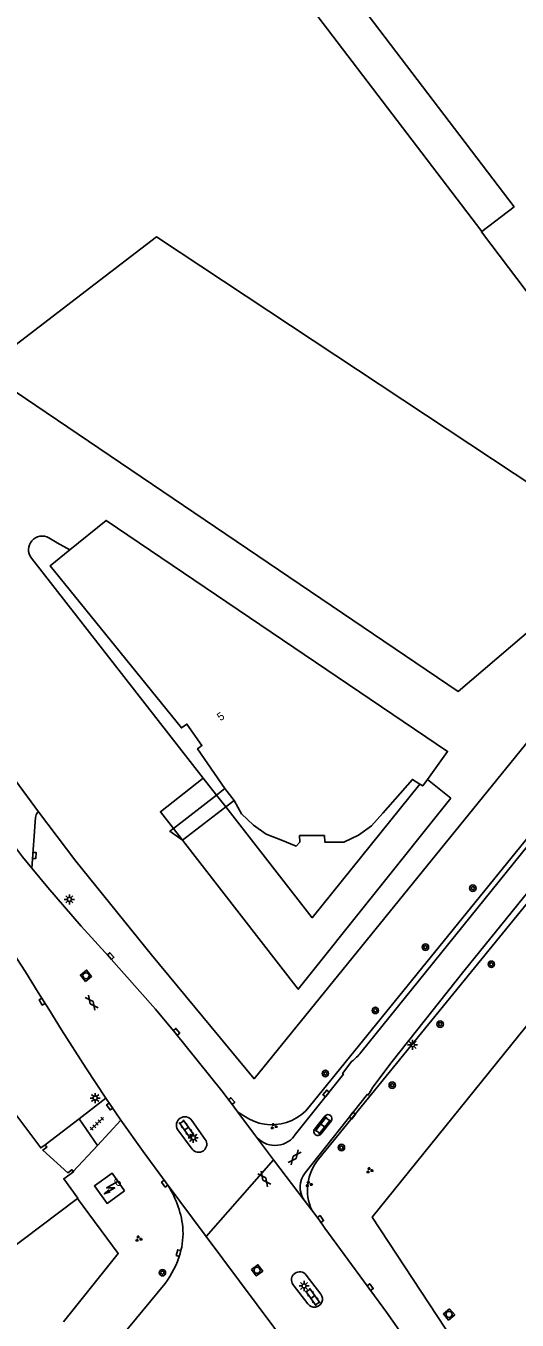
# Model space of a CAD drawing. Extents: x 126000 to 131009, y 393000 to 395500.
# Drawn here: x 130767.6 to 130828.7, y 394018 to 394178.9 of the extents above; entities that cross this region are included whole.
import ezdxf

# ---------------------------------------------------------------- set-up
doc = ezdxf.new("R2010")
doc.units = 0
for name, color, linetype in [('gg-afsc-hekwerk', 7, 'Continuous'), ('gg-afsc-muur', 7, 'Continuous'), ('gg-anno-huisnummerreeks BGT', 7, 'Continuous'), ('gg-bbg-bijgebouw', 7, 'Continuous'), ('gg-bbg-hoofdgebouw', 7, 'Continuous'), ('gg-bbg-onder overbouw', 7, 'Continuous'), ('gg-bbg-pand overbouw', 7, 'Continuous'), ('gg-knt-verharding', 7, 'Continuous'), ('gg-knt-verharding nz', 7, 'Continuous'), ('gg-kntw-bovenkant insteek waterloop', 7, 'Continuous'), ('gg-kntw-kademuur', 7, 'Continuous'), ('gt-grn-groengrens', 7, 'Continuous'), ('gt-grn-weggrens', 7, 'Continuous'), ('gt-symb-boom', 7, 'Continuous'), ('gt-symb-gesloten verharding', 7, 'Continuous'), ('gt-symb-groenvak', 7, 'Continuous'), ('gt-symb-klinker verharding', 7, 'Continuous'), ('gt-symb-kolk', 7, 'Continuous'), ('gt-symb-lichtmast', 7, 'Continuous'), ('gt-symb-rioolschacht', 7, 'Continuous'), ('gt-symb-tegel verharding', 7, 'Continuous'), ('gt-symb-trafo symbool', 7, 'Continuous')]:
    doc.layers.add(name, color=color, linetype=linetype)

# ---------------------------------------------------------------- blocks, each defined once
blk = doc.blocks.new('gt0-KOLK')
at = {"layer": 'gt-symb-kolk'}
blk.add_lwpolyline([(0, 0), (0.38, 0), (0.38, 0.4), (-0.37, 0.4), (-0.37, 0), (0, 0)], dxfattribs=at)
blk = doc.blocks.new('gt0-KL1')
at = {"layer": 'gt-symb-klinker verharding'}
for p, q in [((-1.15, 0.3), (1.15, 0.3)), ((-1, -0.3), (-1, 0.3)), ((-0.5, 0.3), (-0.5, 0.45)), ((0, -0.3), (0, 0.3)), ((0.5, 0.3), (0.5, 0.45)), ((1, -0.3), (1, 0.3)), ((-1.15, -0.3), (1.15, -0.3)), ((-0.5, -0.45), (-0.5, -0.3)), ((0.5, -0.45), (0.5, -0.3))]:
    blk.add_line(p, q, dxfattribs=at)
blk = doc.blocks.new('gt0-BOOM')
at = {"layer": 'gt-symb-boom'}
for radius in [0.4, 0.2]:
    blk.add_circle((0, 0), radius, dxfattribs=at)
blk = doc.blocks.new('gt0-GRVAK')
at = {"layer": 'gt-symb-groenvak'}
for p, q in [((-0.11, 0.19), (-0.23, 0.24)), ((-0.18, 0.15), (0.09, 0.15)), ((-0.09, 0.21), (-0.16, 0.32)), ((-0.05, 0.21), (-0.05, 0.39)), ((0, 0.21), (0.06, 0.32)), ((0.01, 0.19), (0.13, 0.24)), ((0.26, -0.05), (0.2, 0.06)), ((0.3, -0.05), (0.3, 0.13)), ((0.35, -0.05), (0.41, 0.06)), ((-0.25, -0.23), (-0.36, -0.18)), ((-0.32, -0.26), (-0.05, -0.26)), ((-0.23, -0.21), (-0.29, -0.1)), ((-0.18, -0.2), (-0.18, -0.02)), ((-0.14, -0.21), (-0.07, -0.1)), ((-0.12, -0.23), (0, -0.18)), ((0.24, -0.07), (0.12, -0.02)), ((0.17, -0.11), (0.44, -0.11)), ((0.37, -0.07), (0.49, -0.02))]:
    blk.add_line(p, q, dxfattribs=at)
blk = doc.blocks.new('gt0-RS')
at = {"layer": 'gt-symb-rioolschacht'}
blk.add_lwpolyline([(-0.5, -0.5), (0.5, -0.5), (0.5, 0.5), (-0.5, 0.5)], close=True, dxfattribs=at)
blk.add_circle((0, 0), 0.375, dxfattribs=at)
blk = doc.blocks.new('gt0-GESVH1')
at = {"layer": 'gt-symb-gesloten verharding'}
for p, q in [((-0.99, -0.26), (0.01, 0.24)), ((0.01, -0.26), (-0.99, 0.24)), ((0.01, 0.24), (1.01, -0.26)), ((1.01, 0.24), (0.01, -0.26))]:
    blk.add_line(p, q, dxfattribs=at)
blk = doc.blocks.new('gt0-LMAST')
at = {"layer": 'gt-symb-lichtmast'}
for p, q in [((-0.18, 0.17), (-0.45, 0.44)), ((0, 0.25), (0, 0.62)), ((0.17, 0.17), (0.44, 0.44)), ((-0.25, 0), (-0.63, 0)), ((-0.18, -0.18), (-0.45, -0.45)), ((0, -0.25), (0, -0.63)), ((0.44, -0.45), (0.17, -0.18)), ((0.25, 0), (0.62, 0))]:
    blk.add_line(p, q, dxfattribs=at)
blk.add_circle((0, 0), 0.25, dxfattribs=at)
blk = doc.blocks.new('gt0-TEG1')
at = {"layer": 'gt-symb-tegel verharding'}
for p, q in [((-1.12, 0), (1.12, 0)), ((-0.9, -0.25), (-0.9, 0.25)), ((-0.45, -0.25), (-0.45, 0.25)), ((0, -0.25), (0, 0.25)), ((0.45, -0.25), (0.45, 0.25)), ((0.9, -0.25), (0.9, 0.25))]:
    blk.add_line(p, q, dxfattribs=at)
blk = doc.blocks.new('gt0-HSP')
at = {"layer": 'gt-symb-trafo symbool'}
for points in [[(0.77, 0.75), (-0.53, 0), (0.47, 0), (-0.83, -0.75)], [(-0.22, -0.24), (-0.83, -0.75), (-0.08, -0.48)]]:
    blk.add_lwpolyline(points, dxfattribs=at)

msp = doc.modelspace()

# ---------------------------------------------------------------- linework, layer by layer
at = {"layer": 'gg-afsc-hekwerk'}
for p, q in [((130782.38, 394208.28), (130824.29, 394153.36)), ((130769.13, 394081.19), (130766.27, 394085.09))]:
    msp.add_line(p, q, dxfattribs=at)
for points in [[(130847.03, 394110.9), (130795.94, 394047.99), (130783.2, 394063.41), (130773.77, 394075.06), (130769.13, 394081.19)], [(130857.9, 394089.3), (130810.65, 394030.76), (130830.86, 394000)], [(130773.98, 394033.09), (130779.05, 394026.25), (130772.23, 394017.75)]]:
    msp.add_lwpolyline(points, dxfattribs=at)
at = {"layer": 'gg-afsc-muur'}
for p, q in [((130770.42, 394115.26), (130771.45, 394114.66)), ((130771.45, 394114.66), (130773.02, 394113.77)), ((130789.63, 394085.36), (130768.25, 394112.75))]:
    msp.add_line(p, q, dxfattribs=at)
msp.add_arc((130769.58, 394113.79), 1.69, 60.2136, 217.9768, dxfattribs=at)
at = {"layer": 'gg-bbg-bijgebouw'}
msp.add_lwpolyline([(130776.19, 394146.86), (130783.82, 394152.69), (130842.25, 394114.02), (130821.34, 394096.16), (130762.19, 394136.16), (130776.19, 394146.86)], dxfattribs=at)
at = {"layer": 'gg-bbg-hoofdgebouw'}
msp.add_line((130828.31, 394156.42), (130824.29, 394153.36), dxfattribs=at)
for points in [[(130808.18, 394220.62), (130807.84, 394220.37), (130811.77, 394215.21), (130811.85, 394215.26), (130812.68, 394214.15), (130794.75, 394200.51), (130828.31, 394156.42)], [(130847.63, 394122.45), (130824.25, 394153.33), (130824.29, 394153.36)], [(130817.51, 394085.21), (130820.02, 394088.7), (130777.54, 394117.43), (130773.02, 394113.77)], [(130792.3, 394084.07), (130788.93, 394089.02), (130789.46, 394089.43), (130787.6, 394092.1), (130786.91, 394091.62), (130770.59, 394111.8), (130773.02, 394113.77)], [(130816.57, 394084.63), (130815.65, 394085.22), (130811.97, 394081), (130810.56, 394079.46), (130808.92, 394078.27), (130807.11, 394077.41), (130804.76, 394077.41), (130804.69, 394078.23), (130801.6, 394078.23), (130801.65, 394077.42), (130801.19, 394076.93), (130799.27, 394077.72), (130797.47, 394078.39), (130795.89, 394079.53), (130794.4, 394080.93), (130793.46, 394082.6)], [(130816.57, 394084.63), (130816.93, 394084.4), (130817.51, 394085.21)], [(130741.04, 394077.22), (130769.42, 394039.39), (130769.98, 394039.75)], [(130737.87, 394043.54), (130755.87, 394019.46), (130773.98, 394033.09)], [(130769.98, 394039.75), (130770.17, 394039.49), (130769.66, 394039.11), (130772.79, 394036.29), (130773.29, 394036.67), (130773.46, 394036.44)], [(130773.98, 394033.09), (130774.04, 394033.14), (130772.27, 394035.54), (130773.49, 394036.41), (130773.46, 394036.44)], [(130779.82, 394034.06), (130777.67, 394032.48), (130776.08, 394034.66), (130778.28, 394036.25), (130779.82, 394034.06)]]:
    msp.add_lwpolyline(points, dxfattribs=at)
at = {"layer": 'gg-bbg-onder overbouw'}
msp.add_line((130792.3, 394084.07), (130793.46, 394082.6), dxfattribs=at)
at = {"layer": 'gg-bbg-pand overbouw'}
for p, q in [((130791.27, 394083.27), (130792.3, 394084.07)), ((130791.27, 394083.27), (130785.93, 394079.11)), ((130793.46, 394082.6), (130792.42, 394081.8)), ((130787.05, 394077.68), (130792.42, 394081.8))]:
    msp.add_line(p, q, dxfattribs=at)
msp.add_lwpolyline([(130787.05, 394077.68), (130785.47, 394078.76), (130785.93, 394079.11)], dxfattribs=at)
at = {"layer": 'gg-knt-verharding'}
for p, q in [((130769.01, 394081.1), (130769.13, 394081.19)), ((130768.75, 394080.49), (130768.3, 394074.19)), ((130777.52, 394045.56), (130774.18, 394042.99)), ((130779.38, 394042.84), (130777.52, 394045.56)), ((130793.94, 394043.82), (130796.13, 394040.87)), ((130774.18, 394042.99), (130769.98, 394039.75)), ((130776.48, 394039.7), (130779.38, 394042.84)), ((130788.2, 394042.78), (130789.88, 394040.44)), ((130804.75, 394043.35), (130803.51, 394041.77)), ((130804.27, 394041.11), (130805.52, 394042.72)), ((130788.25, 394039.24), (130786.46, 394041.65)), ((130773.46, 394036.44), (130776.48, 394039.7)), ((130790, 394028.37), (130785, 394035.05)), ((130803.14, 394031.62), (130802.17, 394032.89)), ((130800.57, 394014.22), (130790, 394028.37)), ((130802.42, 394023.55), (130804.25, 394021.19)), ((130778.55, 394014.83), (130784.87, 394022.52)), ((130802.64, 394019.99), (130800.79, 394022.37))]:
    msp.add_line(p, q, dxfattribs=at)
for points in [[(130868.2, 394118.01), (130856.33, 394103.62), (130847.32, 394092.59), (130822.05, 394061.38), (130813.14, 394050.14), (130810.73, 394046.93), (130810.15, 394045.96), (130810.04, 394046.05), (130802.3, 394036.29)], [(130809.22, 394051.26), (130830.96, 394078.16), (130853.82, 394106.34), (130853.94, 394106.64), (130853.99, 394106.95)], [(130768.3, 394074.19), (130767.15, 394075.58), (130764, 394079.72), (130759.54, 394085.8)], [(130791.92, 394046.49), (130786.15, 394053.7), (130783.68, 394056.62), (130777.82, 394063.25), (130774.44, 394066.98), (130770.3, 394071.77), (130768.3, 394074.19)], [(130764.2, 394066.33), (130765.89, 394063.79), (130767.53, 394061.27), (130769.11, 394058.73), (130769.75, 394057.68), (130770.42, 394056.64), (130772.01, 394054.08)], [(130777.52, 394045.56), (130775.02, 394049.34), (130772.01, 394054.08)], [(130800.95, 394040.87), (130807.06, 394048.55), (130806.96, 394048.63), (130808.1, 394050.16)], [(130791.92, 394046.49), (130792.84, 394045.27), (130793, 394045.09), (130793.94, 394043.82)], [(130785, 394035.05), (130782.16, 394038.92), (130779.38, 394042.84)], [(130804.76, 394029.42), (130804.04, 394030.43), (130803.14, 394031.62)], [(130804.76, 394029.42), (130812.41, 394018.97), (130813.99, 394016.7), (130815.89, 394013.76), (130819.98, 394007.25)]]:
    msp.add_lwpolyline(points, dxfattribs=at)
for centre, radius, start, end in [((130769.82, 394080.39), 1.07, 138.6022, 174.683), ((130805.43, 394054.02), 4.69, 304.614, 323.8334), ((130787.33, 394042.21), 1.04, 33.3243, 212.6033), ((130805.13, 394043.03), 0.501, 321.7935, 140.2076), ((130798.54, 394042.76), 3.07, 218.1447, 321.7839), ((130803.88, 394041.43), 0.504, 137.9362, 320.1949), ((130789.05, 394039.86), 1.02, 217.2913, 35.1739), ((130804.57, 394034.5), 2.89, 141.8352, 213.849), ((130775.27, 394028.24), 11.88, 6.2599, 34.9456), ((130778.13, 394028.78), 8.98, 343.5907, 4.8262), ((130775.7, 394029.45), 11.5, 322.9308, 343.8039), ((130801.61, 394022.96), 1.01, 36.1409, 215.7295), ((130803.46, 394020.57), 1, 215.2896, 38.1078)]:
    msp.add_arc(centre, radius, start, end, dxfattribs=at)
at = {"layer": 'gg-knt-verharding nz'}
for p, q in [((130798.37, 394037.92), (130796.13, 394040.87)), ((130802.17, 394032.89), (130798.37, 394037.92))]:
    msp.add_line(p, q, dxfattribs=at)
at = {"layer": 'gg-kntw-bovenkant insteek waterloop'}
for p, q in [((130820.43, 394082.87), (130817.51, 394085.21)), ((130787.05, 394077.68), (130785.93, 394079.11))]:
    msp.add_line(p, q, dxfattribs=at)
for points in [[(130789.63, 394085.36), (130784.3, 394081.2), (130785.93, 394079.11)], [(130820.43, 394082.87), (130801.45, 394059.11), (130787.05, 394077.68)]]:
    msp.add_lwpolyline(points, dxfattribs=at)
at = {"layer": 'gg-kntw-kademuur'}
for p, q in [((130791.27, 394083.27), (130789.63, 394085.36)), ((130792.42, 394081.8), (130791.27, 394083.27))]:
    msp.add_line(p, q, dxfattribs=at)
msp.add_lwpolyline([(130816.57, 394084.63), (130803.19, 394068), (130792.42, 394081.8)], dxfattribs=at)
at = {"layer": 'gt-grn-groengrens'}
for points in [[(130803.96, 394037.97), (130822.09, 394060.19), (130846.98, 394090.76), (130881.78, 394133.04), (130889.29, 394141.85), (130896.91, 394150.55), (130904.58, 394159.08)], [(130793.94, 394043.82), (130795.29, 394042.99), (130795.91, 394042.69), (130796.57, 394042.47), (130797.25, 394042.33), (130797.94, 394042.26), (130798.63, 394042.28), (130799.31, 394042.37), (130799.99, 394042.55), (130800.63, 394042.8), (130801.24, 394043.12), (130801.82, 394043.51), (130802.34, 394043.97), (130802.8, 394044.48), (130843.11, 394094.11), (130853.78, 394107.07)]]:
    msp.add_lwpolyline(points, dxfattribs=at)
msp.add_arc((130808.58, 394034.15), 6, 140.4041, 204.8551, dxfattribs=at)
at = {"layer": 'gt-grn-weggrens'}
for p, q in [((130776.48, 394039.7), (130774.18, 394042.99)), ((130790, 394028.37), (130798.37, 394037.92))]:
    msp.add_line(p, q, dxfattribs=at)

# ---------------------------------------------------------------- block references
at = {"layer": 'gt-symb-boom'}
for p in [(130823.16, 394071.69), (130817.26, 394064.35), (130825.46, 394062.23), (130811.03, 394056.48), (130819.09, 394054.78), (130804.81, 394048.64), (130813.13, 394047.19), (130806.81, 394039.43), (130784.55, 394023.86)]:
    msp.add_blockref('gt0-BOOM', p, dxfattribs=at)
at = {"layer": 'gt-symb-gesloten verharding'}
for p, rotation in [((130775.75, 394057.46), -53.130102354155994), ((130800.98, 394038.21), 51.25072308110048), ((130797.22, 394035.53), -53.783115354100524)]:
    msp.add_blockref('gt0-GESVH1', p, dxfattribs=dict(at, rotation=rotation))
at = {"layer": 'gt-symb-groenvak'}
for p in [(130798.39, 394042.06), (130802.75, 394034.88)]:
    msp.add_blockref('gt0-GRVAK', p, dxfattribs=at)
for p, rotation in [((130810.3, 394036.6), 0.6875163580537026), ((130781.58, 394028.08), -0.7448031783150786)]:
    msp.add_blockref('gt0-GRVAK', p, dxfattribs=dict(at, rotation=rotation))
at = {"layer": 'gt-symb-klinker verharding'}
for p, rotation in [((130787.53, 394041.77), -54.60889248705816), ((130804.49, 394042.17), 51.90391462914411), ((130803.26, 394020.84), -54.608892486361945)]:
    msp.add_blockref('gt0-KL1', p, dxfattribs=dict(at, rotation=rotation))
at = {"layer": 'gt-symb-kolk'}
for p, rotation in [((130768.42, 394075.77), -94.14369049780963), ((130777.96, 394063.12), -48.770950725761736), ((130769.75, 394057.68), 121.13079914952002), ((130786.15, 394053.7), -51.009005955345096), ((130793, 394045.09), -49.01346679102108), ((130805.06, 394046.03), 51.53705293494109), ((130778.15, 394044.64), 124.6118063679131), ((130808.02, 394043.52), -128.38245733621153), ((130785, 394035.05), 126.74379669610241), ((130804.04, 394030.43), -54.735569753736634), ((130786.74, 394026.25), 74.99108632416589), ((130810.22, 394021.95), -53.90943276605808)]:
    msp.add_blockref('gt0-KOLK', p, dxfattribs=dict(at, rotation=rotation))
at = {"layer": 'gt-symb-lichtmast'}
for p in [(130772.97, 394070.3), (130815.65, 394052.2), (130776.18, 394045.59), (130788.39, 394040.65), (130802.17, 394022.21)]:
    msp.add_blockref('gt0-LMAST', p, dxfattribs=at)
at = {"layer": 'gt-symb-rioolschacht'}
for p, rotation in [((130775.04, 394060.79), 38.58825564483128), ((130796.32, 394024.16), -53.2562033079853), ((130820.2, 394018.68), -139.54161829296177)]:
    msp.add_blockref('gt0-RS', p, dxfattribs=dict(at, rotation=rotation))
at = {"layer": 'gt-symb-tegel verharding', "rotation": -136.21542825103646}
msp.add_blockref('gt0-TEG1', (130776.4, 394042.39), dxfattribs=at)
at = {"layer": 'gt-symb-trafo symbool'}
msp.add_blockref('gt0-HSP', (130778.14, 394034.41), dxfattribs=at)

# ---------------------------------------------------------------- texts
at = {"layer": 'gg-anno-huisnummerreeks BGT'}
for s, rotation, p in [('5', 35, (130791.77, 394092.44)), ('6', 36.2, (130778.96, 394034.48))]:
    msp.add_text(s, height=1, rotation=rotation, dxfattribs=at).set_placement(p)

doc.saveas('drawing.dxf')
